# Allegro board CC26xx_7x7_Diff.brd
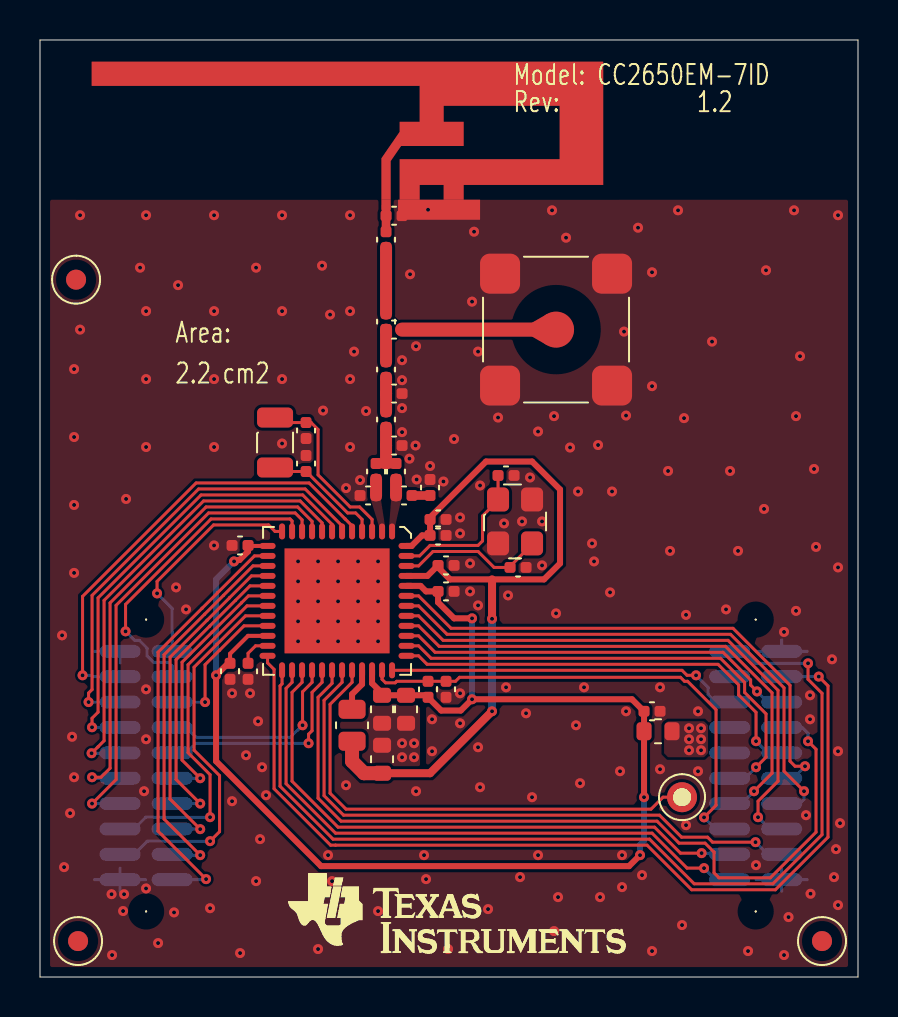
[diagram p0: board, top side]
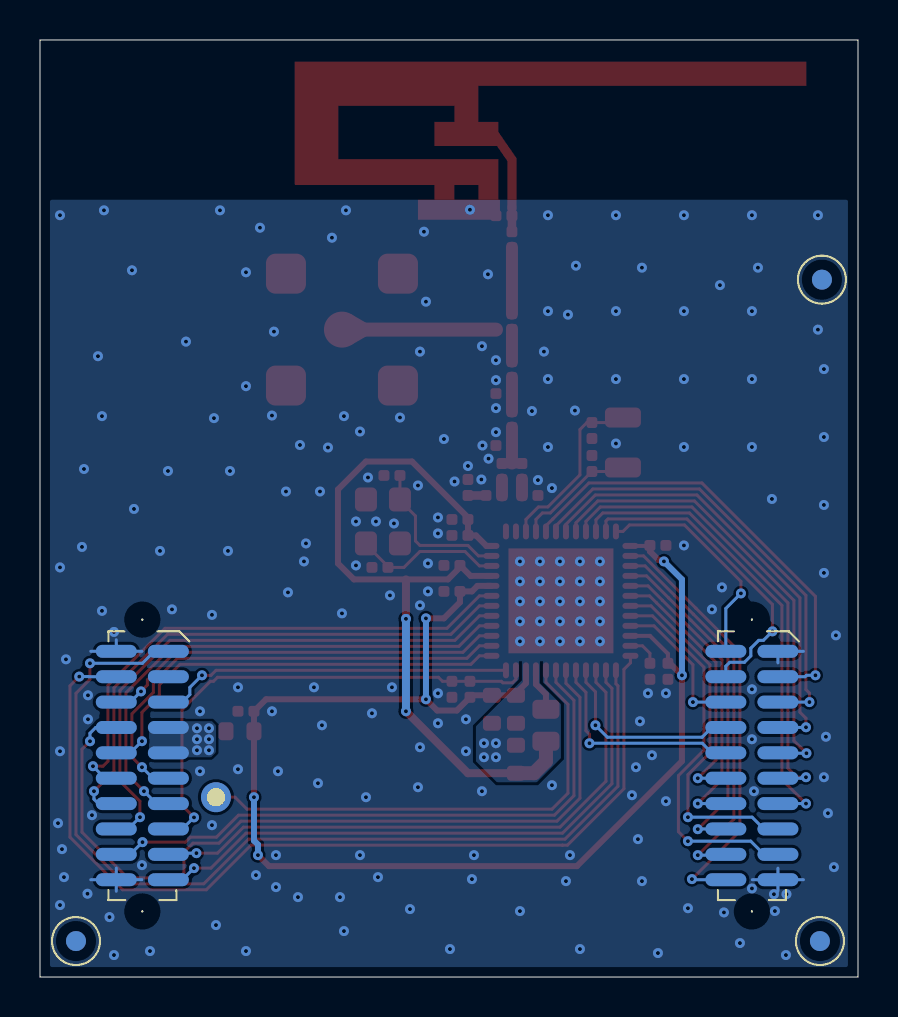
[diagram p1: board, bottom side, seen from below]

Outline 40.9 x 46.9 mm; copper layers: TOP, BOTTOM. Coordinates in mm from the lower left corner of the outline.
Outline path: 0,46.9 0,0 40.9,0 40.9,46.9 0,46.9

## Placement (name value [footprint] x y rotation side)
A1  2.4GHz  [ANTENNA_DN007AN]  17.3 38.65 0 top
C2  2.2uF  [CAPC1005X60L]  30.2 13.3 0 top
C3  100nF  [CAPC1005X60L]  10.4 21.6 180 top
C4  100nF  [CAPC1005X60L]  9.5 15.7 270 top
C5  100nF  [CAPC1005X60L]  19.9 19.3 0 top
C6  4.7uF  [CAPC1608X90L]  17.1 14.1 270 top
C7  100nF  [CAPC1608X90L]  18.3 14.1 270 top
C8  4.7uF  [CAPC1608X90L]  17.1 10.2 90 top
C9  100nF  [CAPC1005X60L]  19.9 20.6 0 top
C10  100nF  [CAPC1005X60L]  19.5 22.9 0 top
C11  1pF  [CAPC1005X60L]  17.8 24.9 90 top
C12  DNM  [CAPC1005X60L]  17.3 26.6 0 top
C13  1.2pF  [CAPC1005X60L]  17.3 29.2 0 top
C14  12pF  [CAPC1005X60L]  17.3 32.4 90 top
C15  DNM  [CAPC1005X60L]  17.3 38.1 0 top
C16  12pF  [CAPC1005X60L]  20.3 22.1 180 top
C17  12pF  [CAPC1005X60L]  13.3 27.75 270 top
C18  12pF  [CAPC1005X60L]  13.3 25.3 90 top
C19  1uF  [CAPC1005X60L]  10.4 15.7 270 top
C20  100nF  [CAPC1005X60L]  20.3 14.8 270 top
C21  1pF  [CAPC1005X60L]  16 24.1 0 top
C22  DNM  [CAPC1005X60L]  23.5 20.5 0 top
C23  DNM  [CAPC1005X60L]  22.9 25.1 0 top
C24  DNM  [CAPC1005X60L]  18.1 32.4 180 top
C31  6.8pF  [CAPC1005X60L]  19.5 24.1 90 top
DIO22  TP_0.9mm_PTH  [TP150_90H]  32.1 9 0 top
FIDU1  FIDU_1MM  [FID100X115]  1.9 1.8 0 top
FIDU2  FIDU_1MM  [FID100X115]  39.1 1.8 0 top
FIDU3  FIDU_1MM  [FID100X115]  1.8 34.9 0 top
FIDU4  FIDU_1MM  [FID100X115]  1.9 1.8 180 bottom
FIDU5  FIDU_1MM  [FID100X115]  39.1 1.8 180 bottom
FIDU6  FIDU_1MM  [FID100X115]  1.8 34.9 180 bottom
FL1  BLM18HE152SN1  [FIL_BLM18HE152SN1DL]  30.2 12.3 0 top
J1  SMA-10V21-TGG  [HUSTSAN_SMA10V21TGGAN]  25.8 32.4 0 top
L1  10uH  [INDC2012X150L]  15.6 13.4 270 top
L11  2.4nH  [INDC1005X60L]  17.8 24.1 0 top
L12  2nH  [INDC1005X60L]  17.3 27.5 90 top
L13  2nH  [INDC1005X60L]  17.3 30 90 top
L21  2.4nH  [INDC1005X60L]  16.8 24.9 90 top
NOREF  -  []  32.36 0 90 top
NOREF#2  -  []  0 44.07 0 top
NOREF#3  -  []  13.4 5.2 0 top
P1  SFM-110-02-S-D-A-K-TR  [SAMTEC_SFM11002AN]  4 16.3 0 bottom
P2  SFM-110-02-S-D-A-K-TR  [SAMTEC_SFM11002AN]  34.48 16.3 0 bottom
R1  100k  [RESC1005X40L]  19.4 14.8 270 top
R12  0  [RESC1005X40L]  17.3 37.3 270 top
U1  CC2650  [QFNFC50P700X700X80-49CL]  17.6 22.3 180 top
Y1  32.768kHz  [XTAL_FC-135N]  11.75 28 270 top
Y2  24MHz  [OSCCC250X320X80-4L]  22.9 23.9 270 top

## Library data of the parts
A1 = ANTENNA_DN007
C2-C5 C9-C24 C31 = CAPACITOR: alternate symbols: (CAPC1005X60L,CAPC1005X60M)
C6-C8 = CAPACITOR: alternate symbols: (CAPC1608X90L,CAPC1608X90M)
DIO22 = TEST_POINT
FIDU1-FIDU6 = FIDMARK
FL1 = FILTER_2PIN: alternate symbols: (FIL_BLM18HE152SN1DL,FIL_BLM18HE152SN1DM)
J1 = CONN_COAX_1+4: alternate symbols: (HUSTSAN_SMA10V21TGGL,HUSTSAN_SMA10V21TGGM)
L1 = INDUCTOR: alternate symbols: (INDC2012X150L,INDC2012X150M)
L11 L21 = INDUCTOR: alternate symbols: (INDC1005X60M,INDC1005X60L)
L12 L13 = INDUCTOR: alternate symbols: (INDC1005X60L,INDC1005X60M)
P1 P2 = CONN_HEADER_2X10_P_S
R1 R12 = RESISTOR: alternate symbols: (RESC1005X40L,RESC1005X40M)
U1 = IC_RF_CC26XX_QFN48_V2: alternate symbols: (QFNFC50P700X700X80-49CL,QFNFC50P700X700X80-49CM)
Y1 = CRYSTAL: alternate symbols: (XTAL_FC-135L,XTAL_FC-135M)
Y2 = XTAL_TSX_3225_V1: alternate symbols: (OSCCC250X320X80-4L,OSCCC250X320X80-4M)

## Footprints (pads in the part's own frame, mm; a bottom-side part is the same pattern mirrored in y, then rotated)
ANTENNA_DN007AN
  rect 0.46x0.5 smd: 1(0,0)
  rect 1x0.5 smd: 2(1.18,0) 3(3.38,0)
CAPC1005X60L
  custom 0.135x0.135 smd: 1(0,0) 2(0.8,0)
CAPC1608X90L
  custom 0.188x0.188 smd: 1(0,0) 2(1.4,0)
FID100X115
  oval 1x1 smd: 1(0,0)
FIL_BLM18HE152SN1DL
  custom 0.188x0.188 smd: 1(0,0) 2(1.4,0)
HUSTSAN_SMA10V21TGGAN
  round 1.801 smd: 1(0,0)
  custom 0.5x0.5 smd: 2(-2.8,-2.8) 3(2.8,-2.8) 4(2.8,2.8) 5(-2.8,2.8)
INDC1005X60L
  custom 0.135x0.135 smd: 1(0,0) 2(0.8,0)
INDC2012X150L
  custom 0.237x0.237 smd: 1(0,0) 2(1.6,0)
OSCCC250X320X80-4L
  custom 0.275x0.275 smd: 1(0,0) 2(2.2,0) 3(2.2,1.7) 4(0,1.7)
QFNFC50P700X700X80-49CL
  oval 0.3x0.8 smd: 1(0,0) 2(0.5,0) 3(1,0) 4(1.5,0) 5(2,0) 6(2.5,0) 7(3,0) 8(3.5,0) 9(4,0) 10(4.5,0) 11(5,0) 12(5.5,0) 25(5.5,6.95) 26(5,6.95) 27(4.5,6.95) 28(4,6.95) 29(3.5,6.95) 30(3,6.95) 31(2.5,6.95) 32(2,6.95) 33(1.5,6.95) 34(1,6.95) 35(0.5,6.95) 36(0,6.95)
  oval 0.8x0.3 smd: 13(6.225,0.725) 14(6.225,1.225) 15(6.225,1.725) 16(6.225,2.225) 17(6.225,2.725) 18(6.225,3.225) 19(6.225,3.725) 20(6.225,4.225) 21(6.225,4.725) 22(6.225,5.225) 23(6.225,5.725) 24(6.225,6.225) 37(-0.725,6.225) 38(-0.725,5.725) 39(-0.725,5.225) 40(-0.725,4.725) 41(-0.725,4.225) 42(-0.725,3.725) 43(-0.725,3.225) 44(-0.725,2.725) 45(-0.725,2.225) 46(-0.725,1.725) 47(-0.725,1.225) 48(-0.725,0.725)
  rect 5.25x5.25 smd: 49(2.75,3.475)
RESC1005X40L
  custom 0.135x0.135 smd: 1(0,0) 2(0.8,0)
SAMTEC_SFM11002AN
  round 0.099 hole 1.501 unplated: (1.302,-1.588) (1.302,13.018)
  oval 2.05x0.65 smd: 1(0,0) 2(2.604,0) 3(0,1.27) 4(2.604,1.27) 5(0,2.54) 6(2.604,2.54) 7(0,3.81) 8(2.604,3.81) 9(0,5.08) 10(2.604,5.08) 11(0,6.35) 12(2.604,6.35) 13(0,7.62) 14(2.604,7.62) 15(0,8.89) 16(2.604,8.89) 17(0,10.16) 18(2.604,10.16) 19(0,11.43) 20(2.604,11.43)
TP150_90H
  round 1.5 hole 0.9: 1(0,0)
XTAL_FC-135N
  custom 0.25x0.25 smd: 1(0,0) 2(2.5,0)

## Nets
GND: A1.2(GND_2) A1.3(GND_3) C2.2 C3.2 C4.2 C5.2 C6.2 C7.2 C8.2 C9.2 C10.2 C12.2 C13.2 C15.2 C16.1 C17.2 C18.2 C19.2 C20.2 C21.1 C22.2 C23.2 C31.2 J1.2 J1.3 J1.4 J1.5 P1.1 P1.19 P2.2 P2.20 U1.49(VSS) Y2.2 Y2.4
VDD_EB: FL1.2 P2.7 P2.9
VDDR: C8.1 C9.1 C10.1 C16.2 L1.2 U1.45(VDDR#45) U1.48(VDDR#48)
VDDS: C2.1 C3.1 C4.1 C5.1 C6.1 C7.1 FL1.1 R1.2 U1.13(VDDS2) U1.22(VDDS3) U1.34(VDDS_DCDC) U1.44(VDDS)
DCDC_SW: L1.1 U1.33(DCDC_SW)
DIO_0: P1.3 U1.5(DIO_0)
DIO_1: P1.5 U1.6(DIO_1)
DIO_2: P1.7 U1.7(DIO_2)
DIO_3: P1.9 U1.8(DIO_3)
DIO_4: P1.11 U1.9(DIO_4)
DIO_5: P1.13 U1.10(DIO_5)
DIO_6: P1.4 U1.11(DIO_6)
DIO_7: P1.2 U1.12(DIO_7)
DIO_8: P1.20 U1.14(DIO_8)
DIO_9: P1.18 U1.15(DIO_9)
DIO_10: P1.16 U1.16(DIO_10)
DIO_11: P1.14 U1.17(DIO_11)
DIO_12: P1.12 U1.18(DIO_12)
DIO_13: P1.15 U1.19(DIO_13)
DIO_14: P1.17 U1.20(DIO_14)
DIO_15: P1.6 U1.21(DIO_15)
DIO_16 / JTAG TDO: P2.19 U1.26(DIO_16)
DIO_17 / JTAG TDI: P2.17 U1.27(DIO_17)
DIO_18: P1.8 U1.28(DIO_18)
DIO_19: P1.10 U1.29(DIO_19)
DIO_20: P2.8 U1.30(DIO_20)
DIO_21: P2.18 U1.31(DIO_21)
DIO_22: DIO22.1 U1.32(DIO_22)
DIO_23: P2.5 U1.36(DIO_23)
DIO_24: P2.10 U1.37(DIO_24)
DIO_25: P2.11 U1.38(DIO_25)
DIO_26: P2.6 U1.39(DIO_26)
DIO_27: P2.13 U1.40(DIO_27)
DIO_28: P2.16 U1.41(DIO_28)
DIO_29: P2.14 U1.42(DIO_29)
DIO_30: P2.12 U1.43(DIO_30)
JTAG_TCK: P2.1 U1.25(JTAG_TCKC)
JTAG_TMS: P2.4 U1.24(JTAG_TMSC)
NRESET: C20.1 P2.15 R1.1 U1.35(RESET_N)
N310466: C23.1 U1.47(X24M_P) Y2.1
N310868: C22.1 U1.46(X24M_N) Y2.3
N314427: C21.2 L21.1 U1.2(RF_N)
N314470: C11.1 L11.1 U1.1(RF_P)
N314514: C31.1 L11.2
N314764: C11.2 C12.1 L12.1 L21.2
N315193: C13.1 L12.2 L13.1
N316022: A1.1(FEED_1) C15.1 R12.1
N316040: C24.1 J1.1
N316649: C19.1 U1.23(DCOUPL)
N316919: C17.1 U1.3(X32K_Q1) Y1.1
N316932: C18.1 U1.4(X32K_Q2) Y1.2
N334495: C14.1 C24.2 L13.2
N356130: C14.2 R12.2

Pads without a net: FIDU1 1; FIDU2 1; FIDU3 1; FIDU4 1; FIDU5 1; FIDU6 1; P2 3

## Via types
v1: diameter 0.5, hole 0.2, TOP to BOTTOM, 257 vias

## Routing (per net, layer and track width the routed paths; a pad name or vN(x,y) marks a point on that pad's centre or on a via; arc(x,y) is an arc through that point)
GND: length 12.5
  TOP w0.15: U1.49 14.88,18.83 v1(14.9,18.8)
  BOTTOM w0.15: P2.20 37.09,5.45 ; P2.20 37.09,4.29 ; P2.20 38.36,4.87 ; P2.20 35.81,4.87 ; 4,15.72 P1.1 2.73,16.3 ; 35.81,16.3 P2.2 ; P2.2 37.09,16.88 ; P2.2 38.36,16.3 ; P1.19 4,5.45 ; P1.19 2.73,4.87 ; P1.19 5.28,4.87 ; P1.19 4,4.29
  vias: v1(1.1,17.1) v1(1.2,5.5) v1(1.5,8.2) v1(1.6,12.02) v1(1.7,30.42) v1(1.7,27.02) v1(1.7,23.62) v1(1.7,20.22) v1(1.7,10) v1(2,38.12) v1(2,32.4) v1(3.58,4.14) v1(3.6,1.1) v1(4.2,4.14) v1(4.16,3.3) v1(4.3,23.92) v1(5,35.5) v1(5.2,9.3) v1(5.3,38.12) v1(5.3,33.33) v1(5.3,29.92) v1(5.3,26.52) v1(5.3,14.4) v1(5.3,11.9) v1(5.3,4.43) v1(5.9,1.7) v1(6.7,3.23) v1(6.8,19.5) v1(6.9,34.62) v1(7.3,18.4) v1(8.5,3.44) v1(8.7,38.12) v1(8.7,33.33) v1(8.7,29.92) v1(8.7,26.52) v1(8.7,21.6) v1(9.6,14.2) v1(9.6,8.8) v1(10,1.2) v1(10.3,11.1) v1(10.5,14.2) v1(10.8,35.5) v1(10.8,4.8) v1(10.9,12.8) v1(11,6.9) v1(11.1,10.5) v1(11.3,9.1) v1(12.1,38.12) v1(12.1,33.33) v1(12.1,29.92) v1(12.1,26.7) v1(12.9,20.8) v1(12.9,19.8) v1(12.9,18.8) v1(12.9,17.8) v1(12.9,16.8) v1(13.9,20.8) v1(13.9,19.8) v1(13.9,18.8) v1(13.9,17.8) v1(13.9,16.8) v1(13.9,1.4) v1(14.1,35.6) v1(14.15,28.35) v1(14.4,6.1) v1(14.5,33.15) v1(14.6,4.8) v1(14.9,20.8) v1(14.9,19.8) v1(14.9,17.8) v1(14.9,16.8) v1(15.3,24.47) v1(15.3,9.6) v1(15.5,38.12) v1(15.5,33.33) v1(15.5,29.92) v1(15.5,26.52) v1(15.7,31.3) v1(15.9,20.8) v1(15.9,19.8) v1(15.9,18.8) v1(15.9,17.8) v1(15.9,16.8) v1(16,24.87) v1(16.3,28.33) v1(16.9,20.8) v1(16.9,19.8) v1(16.9,18.8) v1(16.9,17.8) v1(16.9,16.8) v1(16.9,3.3) v1(18.1,30.87) v1(18.1,29.87) v1(18.1,28.47) v1(18.1,27.27) v1(18.1,11.7) v1(18.1,11) v1(18.5,35.17) v1(18.47,25.94) v1(18.7,11.7) v1(18.7,11) v1(18.8,31.57) v1(18.78,26.6) v1(18.83,24.9) v1(18.8,9.3) v1(19.2,6.1) v1(19.3,4.9) v1(19.4,38.4) v1(19.5,25.58) v1(19.6,12.9) v1(19.6,11.3) v1(20.17,24.8) v1(20.4,1.4) v1(20.7,26.92) v1(21,23) v1(21,22.2) v1(21,14.2) v1(21,12.7) v1(21.5,20.7) v1(21.5,19.3) v1(21.6,33.8) v1(21.7,37.3) v1(21.9,31.3) v1(21.9,18.6) v1(21.9,11.5) v1(22,24.6) v1(22,9.5) v1(22.4,3.4) v1(22.9,28) v1(23.2,22.7) v1(23.3,14.5) v1(23.4,19.1) v1(24,5) v1(24.1,22.8) v1(24.3,13.2) v1(24.5,25) v1(24.6,9) v1(24.9,27.3) v1(24.9,6.1) v1(25.1,22.8) v1(25.1,20.6) v1(25.6,38.37) v1(25.7,28.07) v1(25.7,2.3) v1(25.8,18.2) v1(25.9,4) v1(26.3,37) v1(26.5,26.5) v1(26.8,12.6) v1(26.9,24.3) v1(27,9.7) v1(27.2,14.5) v1(27.6,21.7) v1(27.7,20.8) v1(27.9,26.62) v1(28,4) v1(28.5,19.25) v1(28.6,24.3) v1(29,10.3) v1(29.1,6.1) v1(29.1,4.5) v1(29.2,32.3) v1(29.3,28.1) v1(29.3,13.3) v1(29.9,37.5) v1(30.1,5.1) v1(30.6,35.27) v1(30.6,29.57) v1(30.6,1.3) v1(31,14.5) v1(31,10.4) v1(31.4,25.33) v1(31.5,21.33) v1(31.9,38.37) v1(32.1,2.6) v1(32.2,27.97) v1(32.3,18.12) v1(32.3,7.6) v1(32.9,13.3) v1(32.9,10.3) v1(33.6,31.8) v1(34.3,18.4) v1(34.5,25.33) v1(34.9,21.33) v1(35.4,1.3) v1(35.8,5.6) v1(36.2,23.42) v1(36.3,35.37) v1(37.2,17.27) v1(37.2,1.1) v1(37.43,3) v1(37.7,38.37) v1(37.8,28.07) v1(37.8,18.33) v1(38,31.07) v1(38.3,8.1) v1(38.5,14.1) v1(38.5,12.9) v1(38.53,4.17) v1(38.7,25.42) v1(38.8,21.52) v1(39.6,15.9) v1(39.7,5) v1(39.8,6.4) v1(39.9,38.12) v1(39.9,20.5) v1(39.9,11.3) v1(39.9,3.6) v1(40,7.7)
VDD_EB:
  vias: v1(32.45,12.45) v1(32.45,11.9) v1(32.45,11.35) v1(33.05,12.45) v1(33.05,11.9) v1(33.05,11.35)
VDDR: length 38.9
  TOP w0.3: U1.45 19.37,20.08 19.9,20.6 C9.1 19.9,20.5 20.5,19.9 25.2,19.9 26,20.7 26,24.4 24.6,25.8 22.3,25.8 19.5,23 C10.1 C16.2 19.1,22.1 18.58,21.58 U1.48
  TOP w0.4: v1(22.6,17.93) 22.6,19.9 ; C8.1 19.5,10.2 v1(22.6,13.3)
  TOP w0.7: L1.2 15.6,10.8 16.2,10.2 C8.1
  BOTTOM w0.4: v1(22.6,13.3) v1(22.6,17.93)
VDDS: length 70.8
  TOP w0.2: C4.1 9.5,16.18 10.4,17.08 U1.22 ; C3.1 10.43,21.58 U1.13
  TOP w0.3: v1(9.7,20.8) 9.78,20.87 9.98,20.87 10.4,21.3 C3.1 ; v1(30,6.1) 29.45,5.55 14.05,5.55 8.8,10.8 v1(8.8,15.1) 9.41,15.7 C4.1 ; v1(21.6,17.95) 20.71,17.95 19.9,18.75 C5.1 19.3,19.3 19.03,19.58 U1.44 ; U1.34 16.6,14.7 17.1,14.2 C6.1 C7.1 19.3,14.1 R1.2 19.4,13.99 20.06,13.34 21.04,13.34 v1(21.6,13.9) 29.6,13.9 30.2,13.3 C2.1 FL1.1 v1(30.2,9)
  BOTTOM w0.3: v1(8.8,15.1) 8.8,19.9 v1(9.7,20.8) ; v1(21.6,13.9) v1(21.6,17.95) ; v1(30.2,9) 30.2,6.83 30,6.63 v1(30,6.1)
DCDC_SW: length 2.2
  TOP w0.3: U1.33 16.1,14.65 15.6,14.15 L1.1
DIO_0: length 22.8
  TOP w0.15: v1(2.13,15.1) 2.13,19.05 7.8,24.72 13.46,24.72 15.26,22.92 15.6,22.58 U1.5
  BOTTOM w0.15: v1(2.13,15.1) 2.58,15.1 2.65,15.03 P1.3
DIO_1: length 22.7
  TOP w0.15: U1.6 15.1,22.58 13.26,24.42 7.93,24.42 2.6,19.1 2.6,14.39 2.43,14.21 v1(2.43,13.76)
  BOTTOM w0.15: v1(2.43,13.76) P1.5
DIO_2: length 22.8
  TOP w0.15: U1.7 14.6,22.66 13.14,24.12 8.05,24.12 2.9,18.97 2.9,13.25 2.6,12.95 v1(2.6,12.5)
  BOTTOM w0.15: P1.7 2.81,12.49 2.8,12.5 v1(2.6,12.5)
DIO_3: length 23.2
  TOP w0.15: U1.8 14.1,22.73 13.01,23.83 8.18,23.83 3.2,18.85 3.2,11.82 2.9,11.52 v1(2.58,11.2)
  BOTTOM w0.15: P1.9 3.98,11.2 v1(2.58,11.2)
DIO_4: length 23.7
  TOP w0.15: U1.9 13.6,22.81 12.89,23.52 8.3,23.52 3.5,18.72 3.5,10.45 3.05,10 v1(2.6,10)
  BOTTOM w0.15: v1(2.6,10) 2.8,10 2.85,9.95 P1.11
DIO_5: length 23.8
  TOP w0.15: v1(2.6,8.68) 3.8,9.88 3.8,18.6 8.43,23.22 12.76,23.22 13.1,22.88 U1.10
  BOTTOM w0.15: P1.13 v1(2.6,8.68)
DIO_6: length 15.8
  TOP w0.15: v1(4.28,17.3) 4.28,18.65 8.55,22.92 12.5,22.92 12.6,22.83 U1.11
  BOTTOM w0.15: v1(4.28,17.3) 4.73,16.85 4.96,16.85 5.36,16.46 5.36,16.07 5.68,15.75 6.42,15.75 6.61,15.56 P1.4
DIO_7: length 11.4
  TOP w0.15: U1.12 11.75,22.3 11.43,22.62 8.68,22.62 5.85,19.8 v1(5.85,19.2)
  BOTTOM w0.15: v1(5.85,19.2) 6.61,18.45 P1.2
DIO_8: length 21.5
  TOP w0.15: v1(8.3,4.9) 5.9,7.3 5.9,16.26 8.11,18.46 10.72,21.08 U1.14
  BOTTOM w0.15: v1(8.3,4.9) 8.27,4.87 P1.20
DIO_9: length 19.2
  TOP w0.15: v1(8.01,6.1) 6.2,7.91 6.2,16.13 8.23,18.16 9.18,19.1 9.18,19.1 10.65,20.58 U1.15
  BOTTOM w0.15: P1.18 6.65,6.1 v1(8.01,6.1)
DIO_10: length 17.2
  TOP w0.15: v1(8.01,7.4) 6.5,8.91 6.5,16.01 8.36,17.86 8.36,17.86 9.48,18.98 9.48,18.98 10.57,20.08 U1.16
  BOTTOM w0.15: v1(8.01,7.4) 7.84,7.4 7.84,7.41 P1.16
DIO_11: length 15.2
  TOP w0.15: U1.17 10.5,19.58 9.78,18.85 8.48,17.56 8.48,17.56 6.8,15.88 6.8,9.89 v1(8.01,8.68)
  BOTTOM w0.15: v1(8.01,8.68) P1.14
DIO_12: length 13.2
  TOP w0.15: v1(8.01,9.95) 7.1,10.86 7.1,15.76 8.61,17.26 10.42,19.08 U1.18
  BOTTOM w0.15: v1(8.01,9.95) P1.12
DIO_13: length 18
  TOP w0.15: v1(8.5,8) 8.5,10.13 7.4,11.23 7.4,15.63 8.73,16.96 10.35,18.58 U1.19
  BOTTOM w0.15: P1.15 4.7,7.41 5.29,8 v1(8.5,8)
DIO_14: length 18.9
  TOP w0.15: v1(8.5,6.8) 8.98,7.27 8.98,10.08 7.7,11.35 7.7,15.51 8.86,16.66 8.86,16.66 10.27,18.08 U1.20
  BOTTOM w0.15: P1.17 4.7,6.14 5.36,6.8 v1(8.5,6.8)
DIO_15: length 7.4
  TOP w0.15: U1.21 10.2,17.58 8.98,16.36 8.98,16.36 8.25,15.63 v1(8.25,13.76)
  BOTTOM w0.15: P1.6 v1(8.25,13.76)
DIO_16 / JTAG TDO: length 30
  TOP w0.15: U1.26 12.6,14.75 12.3,14.45 12.3,9.67 14.78,7.2 30.6,7.2 32.35,5.45 v1(33.2,5.45)
  BOTTOM w0.15: P2.19 33.78,4.87 v1(33.2,5.45)
DIO_17 / JTAG TDI: length 29.2
  TOP w0.15: U1.27 13.1,14.75 12.6,14.25 12.6,9.8 14.9,7.5 30.73,7.5 32.03,6.2 v1(33.08,6.2)
  BOTTOM w0.15: v1(33.08,6.2) 33.72,6.2 33.78,6.14 P2.17
DIO_18: length 9.9
  TOP w0.15: U1.28 13.6,14.75 13.13,14.27 v1(13.13,12.6)
  BOTTOM w0.15: P1.8 7.31,12.49 7.8,12 12.53,12 v1(13.13,12.6)
DIO_19: length 10.9
  TOP w0.15: v1(13.43,11.7) 13.43,12.15 13.6,12.33 13.6,14.25 14.1,14.75 U1.29
  BOTTOM w0.15: v1(13.43,11.7) 7.79,11.7 7.31,11.22 P1.10
DIO_20: length 41.3
  TOP w0.15: U1.30 14.6,14.7 13.9,14 13.9,8.95 15.05,7.8 30.85,7.8 31.95,6.7 33.25,6.7 33.7,6.25 33.7,5.22 33.95,4.97 36.52,4.97 38.8,7.25 38.8,11.4 v1(38.4,11.8)
  BOTTOM w0.15: v1(38.4,11.8) 38.4,12.2 38.11,12.49 P2.8
DIO_21: length 30.7
  TOP w0.15: v1(35.78,6.75) 33.63,6.75 33.38,7 32.08,7 30.98,8.1 15.18,8.1 14.2,9.08 14.2,13.85 15.1,14.75 U1.31
  BOTTOM w0.15: v1(35.78,6.75) 36.39,6.14 P2.18
DIO_22: length 24.8
  TOP w0.15: U1.32 15.6,14.75 14.5,13.65 14.5,9.2 15.3,8.4 30.55,8.4 31.15,9 DIO22.1
DIO_23: length 17.7
  TOP w0.15: U1.36 32.1,15.35 32.35,15.1 v1(32.8,15.1)
  BOTTOM w0.15: v1(32.8,15.1) 33.41,14.49 33.41,14.13 33.78,13.76 P2.5
DIO_24: length 21.9
  TOP w0.15: U1.37 18.93,16.08 19.36,15.65 33.9,15.65 34.93,14.62 34.93,14.12 35.8,13.25 v1(35.8,11.8)
  BOTTOM w0.15: P2.10 36.39,11.22 v1(35.8,11.8)
DIO_25: length 24.1
  TOP w0.15: U1.38 18.93,16.58 19.56,15.95 34.03,15.95 35.23,14.74 35.23,14.24 36.3,13.17 36.3,11 v1(35.8,10.5)
  BOTTOM w0.15: P2.11 35.25,9.95 v1(35.8,10.5)
DIO_26: length 20.3
  TOP w0.15: U1.39 18.93,17.08 19.76,16.25 34.15,16.25 35.53,14.87 35.53,14.61 v1(35.85,14.29)
  BOTTOM w0.15: v1(35.85,14.29) 36.39,13.76 P2.6
DIO_27: length 26.4
  TOP w0.15: U1.40 18.93,17.58 19.96,16.55 34.28,16.55 36.6,14.22 36.6,10.2 v1(35.7,9.3)
  BOTTOM w0.15: v1(35.7,9.3) 35.08,8.68 P2.13
DIO_28: length 28.3
  TOP w0.15: U1.41 18.93,18.08 20.16,16.85 34.4,16.85 36.9,14.35 36.9,9.8 35.9,8.8 v1(35.9,8)
  BOTTOM w0.15: P2.16 37.08,7.4 36.5,7.4 v1(35.9,8)
DIO_29: length 27.8
  TOP w0.15: v1(38.2,9.3) 37.2,10.3 37.2,14.47 34.53,17.15 20.36,17.15 18.93,18.58 U1.42
  BOTTOM w0.15: v1(38.2,9.3) 38.2,8.9 37.98,8.68 P2.14
DIO_30: length 27.1
  TOP w0.15: U1.43 18.93,19.08 20.56,17.45 34.65,17.45 37.5,14.6 37.5,10.8 37.75,10.55 v1(38.25,10.55)
  BOTTOM w0.15: v1(38.25,10.55) 37.65,9.95 P2.12
JTAG_TCK: length 49
  TOP w0.15: U1.25 12.1,14.67 12,14.57 12,9.55 14.65,6.9 30.48,6.9 32.71,4.67 36.64,4.67 39.1,7.12 39.1,14.2 38.4,14.9 v1(38.4,15.7)
  BOTTOM w0.15: P2.1 35.18,16.3 35.78,15.7 v1(38.4,15.7)
JTAG_TMS: length 47.8
  TOP w0.15: U1.24 11.38,15.72 11.7,15.4 11.7,9.42 14.53,6.6 14.78,6.6 14.78,6.6 30.35,6.6 32.59,4.37 36.77,4.37 39.4,7 39.4,14.57 v1(38.94,15.04)
  BOTTOM w0.15: v1(38.94,15.04) 38.49,15.04 38.48,15.03 P2.4
NRESET: length 25.2
  TOP w0.15: U1.35 17.1,14.9 17.28,14.72 17.76,14.72 17.84,14.8 R1.1 C20.1 20.78,14.8 20.98,15 32.03,15 32.23,14.8 32.38,14.8 33.8,13.38 33.8,8.59 v1(33.2,7.99)
  BOTTOM w0.15: v1(33.2,7.99) 33.78,7.41 P2.15
N310466: length 7.9
  TOP w0.15: U1.47 18.98,21.08 19.5,21.6 21.9,21.6 22.13,21.83 22.13,23.08 22.9,23.85 ; 22.9,23.85 22.9,23.7 ; 22.9,23.85 Y2.1 C23.1
N310868: length 7.5
  TOP w0.15: 23.5,20.55 24.6,21.65 Y2.3 ; 23.5,20.55 23.45,20.5 22.7,20.5 21.91,21.3 19.65,21.3 18.93,20.58 U1.46 ; 23.5,20.55 C22.1
N314427: length 0.8
  TOP w0.6: C21.2 L21.1
N314470: length 0.8
  TOP w0.6: C11.1 L11.1
N314514: length 0.9
  TOP w0.43: C31.1 L11.2
N314764: length 2.8
  TOP w0.5: L21.2 C11.2
  TOP w0.6: L12.1 C12.1 17.3,25.7
N315193: length 1.7
  TOP w0.6: L13.1 C13.1 L12.2
N316022: length 1.3
  TOP w0.15: A1.1 17.3,38.58
  TOP w0.43: R12.1 C15.1 17.3,38.58
N316040: length 7.7
  TOP w0.7: C24.1 J1.1
N316649: length 1.6
  TOP w0.15: C19.1 10.4,16.2 10.78,16.58 U1.23
N316919: length 9
  TOP w0.15: U1.3 16.6,22.9 15.98,23.52 15.51,23.52 13.9,25.13 13.9,27.4 13.55,27.75 ; 13.55,27.75 13.5,27.8 ; 13.55,27.75 C17.1 12,27.75 Y1.1
N316932: length 6
  TOP w0.15: U1.4 16.1,22.9 15.78,23.22 15.38,23.22 13.31,25.3 C18.1 11.95,25.3 Y1.2
N334495: length 1.6
  TOP w0.6: C24.2 L13.2
N356130: length 3.3
  TOP w0.6: C14.2 R12.2

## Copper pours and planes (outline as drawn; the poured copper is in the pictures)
GND on TOP (solid shape): 22,37.9 17.9,37.9 17.9,38.9 22,38.9
GND on TOP (solid shape): 28.16,39.64 21.18,39.64 21.18,38.9 20.18,38.9 20.18,39.64 18.98,39.64 18.98,38.9 17.98,38.9 17.98,40.93 25.98,40.93 25.98,43.6 20.18,43.6 20.18,42.8 21.18,42.8 21.18,41.59 18.06,41.59 17.53,40.83 17.53,38.9 17.07,38.9 17.07,40.98 17.98,42.3 17.98,42.8 18.98,42.8 18.98,44.6 2.58,44.6 2.58,45.81 28.16,45.81
GND on TOP: 0.5,0.5 0.5,38.9 40.4,38.9 40.4,0.5 ; 11 cut-outs
GND on BOTTOM: 0.5,0.5 0.5,38.9 40.4,38.9 40.4,0.5 ; 9 cut-outs
VDD_EB on TOP: 31.4,12.8 33.2,12.8 33.4,12.6 33.4,11.2 33.2,11 31.4,11 31.2,11.2 31.2,12.6
VDD_EB on BOTTOM: 32.3,12.8 35.2,12.8 35.45,12.55 35.45,11.15 35.3,11 32.35,11 32.1,11.25 32.1,12.6
N314427 on TOP: 16.54,24.3 16.55,23.85 16.95,22.55 16.95,22.1 17.25,22.1 17.25,22.55 17.05,23.85 17.05,24.3
N314470 on TOP: 18.05,24.3 18.05,23.85 17.75,22.55 17.75,22.1 17.45,22.1 17.45,22.55 17.55,23.85 17.55,24.3

Small or netless copper shapes (teardrops, artwork), in the pictures only: 1 on TOP

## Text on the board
Ref Des/Silkscreen Top: Area: | 2.2 cm2 | Model: CC2650EM-7ID | Rev:            1.2
XSECTION_CHART: L1: TOP CONDUCTOR - COPPER 0.035 MM | *  DIELECTRIC - FR-4 0.73 MM | L2: BOTTOM CONDUCTOR - COPPER 0.035 MM | DESIGN CROSS SECTION CHART | ___________________________ | TOTAL THICKNESS 0.8 MM
User.5: FIGURE | SIZE | 0.2 | 0.9 | 1.501 | DRILL CHART: TOP to BOTTOM | ALL UNITS ARE IN MILLIMETERS | PLATED | NON-PLATED | QTY | 232 | 25 | 1 | 4
